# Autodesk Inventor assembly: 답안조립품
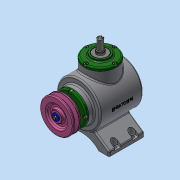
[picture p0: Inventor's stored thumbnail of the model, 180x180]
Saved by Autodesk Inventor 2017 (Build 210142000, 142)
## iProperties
Part Number: 답안조립품
Material: 일반
Document SubType Name: Assembly
Designer: MRC
Author: MRC
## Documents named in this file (17)
- C:\Users\MRC\OneDrive\바탕 화면\730108V1007\답안조립품.iam
- C:\Users\MRC\OneDrive\바탕 화면\730108V1007\본체.ipt
- C:\Users\MRC\OneDrive\바탕 화면\730108V1007\V-벨트풀리.ipt
- C:\Users\MRC\OneDrive\바탕 화면\730108V1007\메인 베벨기어.ipt
- C:\Users\MRC\OneDrive\바탕 화면\730108V1007\메인 축.ipt
- 메인 축.ipt
- C:\Users\MRC\OneDrive\바탕 화면\730108V1007\베어링 6203.ipt
- C:\Users\MRC\OneDrive\바탕 화면\730108V1007\볼트 M4 x 10.ipt
- C:\Users\MRC\OneDrive\바탕 화면\730108V1007\서브 베벨기어.ipt
- C:\Users\MRC\OneDrive\바탕 화면\730108V1007\서브 축.ipt
- 서브 축.ipt
- C:\Users\MRC\OneDrive\바탕 화면\730108V1007\오일실 17 x 32 x 8.ipt
- C:\Users\MRC\OneDrive\바탕 화면\730108V1007\와셔 4 x 16.ipt
- C:\Users\MRC\OneDrive\바탕 화면\730108V1007\육각볼트 M4 x 8.ipt
- C:\Users\MRC\OneDrive\바탕 화면\730108V1007\커버.ipt
- C:\Users\MRC\OneDrive\바탕 화면\730108V1007\키 4 x 4 x 14.ipt
- C:\Users\MRC\OneDrive\바탕 화면\730108V1007\키 5 x 5 x 14.ipt
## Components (1 placed, 1 different names)
1. V-벨트풀리:1
